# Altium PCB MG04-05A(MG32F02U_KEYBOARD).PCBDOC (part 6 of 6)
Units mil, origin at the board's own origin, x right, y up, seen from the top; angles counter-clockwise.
Board outline 17912.8 x 10422.68 mil, 2 copper layers (Top Layer, Bottom Layer); 623 components, 347 nets, 1816 pads, 821 vias.
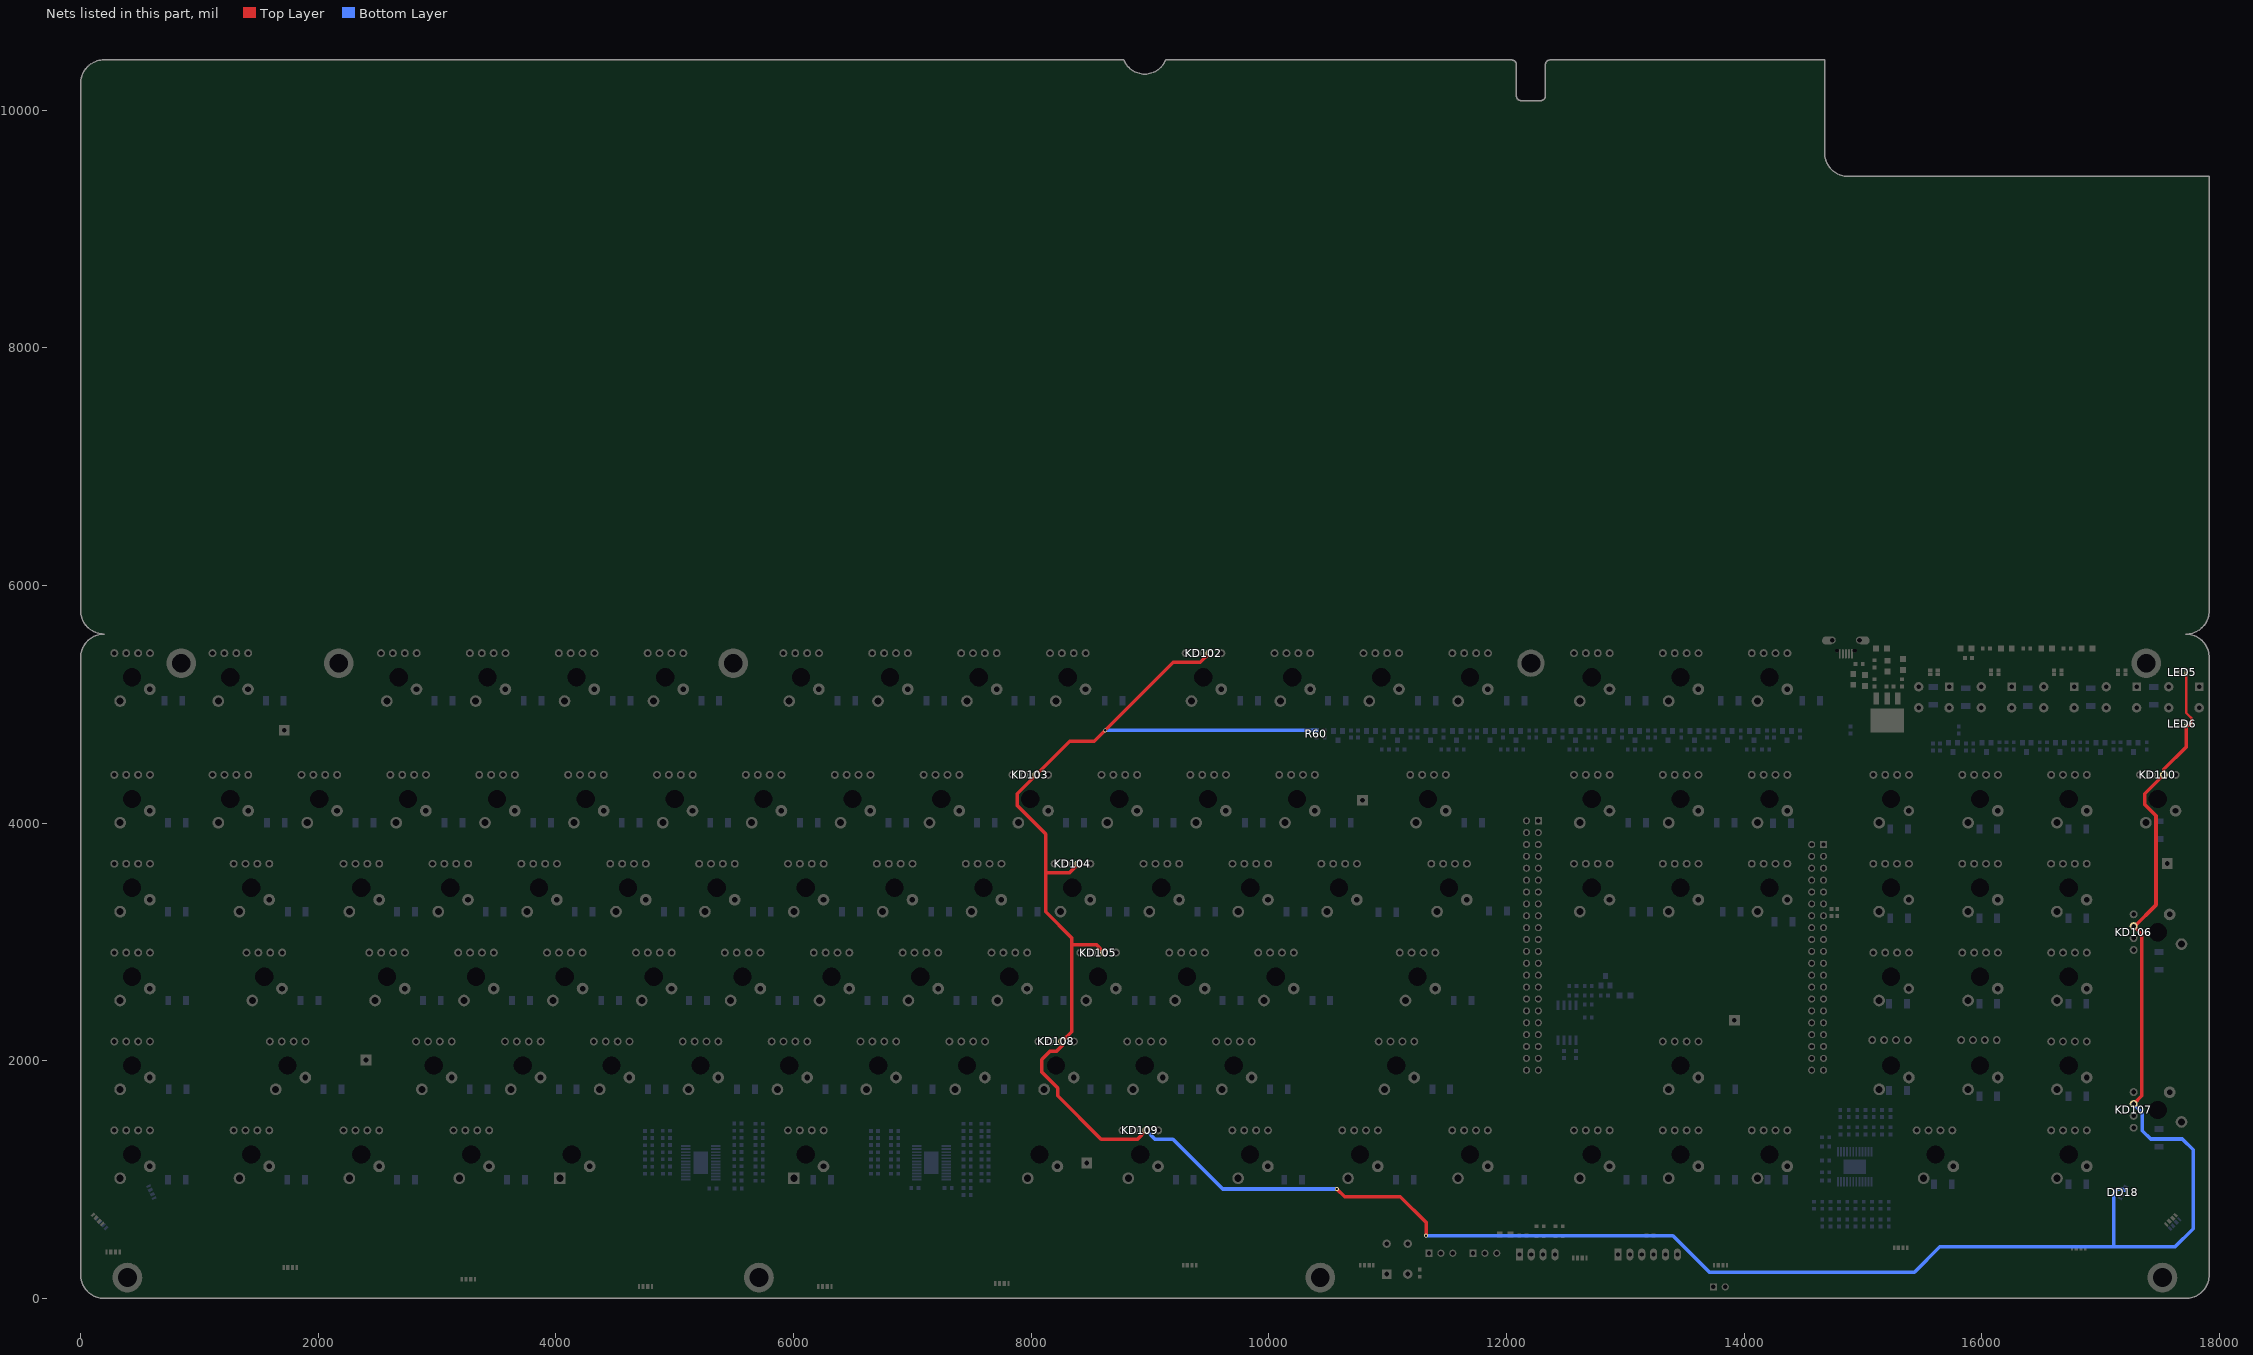
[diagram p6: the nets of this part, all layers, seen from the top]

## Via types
v1: diameter 30, hole 12, Top Layer to Bottom Layer, tented both sides, 273 vias
v2: diameter 26, hole 16, Top Layer to Bottom Layer, tented both sides, 181 vias
v3: diameter 26, hole 12, Top Layer to Bottom Layer, tented both sides, 165 vias
v4: diameter 33, hole 20, Top Layer to Bottom Layer, tented both sides, 61 vias
v5: diameter 25, hole 12, Top Layer to Bottom Layer, tented both sides, 47 vias
v6: diameter 20, hole 12, Top Layer to Bottom Layer, tented both sides, 40 vias
v7: diameter 30, hole 16, Top Layer to Bottom Layer, tented both sides, 30 vias
v8: diameter 28, hole 16, Top Layer to Bottom Layer, tented both sides, 12 vias
v9: diameter 35, hole 20, Top Layer to Bottom Layer, tented both sides, 5 vias
v10: diameter 25, hole 16, Top Layer to Bottom Layer, tented both sides, 3 vias
v11: diameter 40, hole 12, Top Layer to Bottom Layer, tented both sides, 3 vias
v12: diameter 40, hole 20, Top Layer to Bottom Layer, tented both sides, 1 vias

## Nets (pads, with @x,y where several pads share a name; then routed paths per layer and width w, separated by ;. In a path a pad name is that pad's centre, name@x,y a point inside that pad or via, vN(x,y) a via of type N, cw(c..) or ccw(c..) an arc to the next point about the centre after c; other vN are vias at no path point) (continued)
V_11: DD18.1 KD102.1 KD103.1 KD104.1 KD105.1 KD106.1 KD107.1 KD108.1 KD109.1 KD110.1 LED5.1 LED6.1 R60.2 | length 24323.9
  Top Layer w20: LED6.1@17718.5,4818.27 17747,4818.27 17762,4833.27 17762,4885.7 17718.5,4929.2 LED5.1@17718.5,5253.27
  Top Layer w30: KD103.1@8042.3,4390.85 KD103.1@8042.3,4406.2 ; 8341.77,2540.1 8341.77,2977.8 ; KD104.1@8396.72,3657.8 8321.72,3582.8 8121.77,3582.8 ; KD105.1@8613.21,2910.2 8545.61,2977.8 8341.77,2977.8 ; KD109.1@8967.56,1414.1 8893.45,1340 8587,1340 8222,1705 8222,1770 8087,1905 8087,2010 8157,2080 8212,2080 8258.9,2126.89 KD108.1@8258.9,2162.1 8341.77,2244.98 8341.77,2977.8 ; KD102.1@9499.16,5429.8 9422.16,5352.8 9193.92,5352.8 8528.92,4687.8 8323.9,4687.8 KD103.1@8042.3,4406.2 ; v4(10571.85,920.7) 10636.85,855.7 11105.97,855.7 11321.85,639.82 v4(11321.85,527.8) ; KD106.1@17274.6,3121.25 KD106.1@17281.23,3127.88 ; KD107.1@17276.48,1636.37 17344.6,1704.48 17344.6,3064.52 KD106.1@17281.23,3127.88 ; KD106.1@17276.68,3132.43 KD106.1@17281.23,3127.88 ; LED6.1@17718.5,4811.7 17718.5,4640.15 17530.07,4451.72 17530.07,4406.72 17369.6,4246.25 17369.6,4156.25 17464.6,4061.25 17464.6,3311.25 KD106.1@17281.23,3127.88 ; KD103.1@8042.3,4406.2 7881.77,4245.67 7881.77,4147.8 8121.77,3907.8 8121.77,3582.8 ; 8121.77,3582.8 8121.77,3252.8 8341.77,3032.8 8341.77,2977.8
  Bottom Layer w30: v4(8622,4780) R60.2@10400,4780 ; KD109.1@8960.22,1414.1 KD109.1@8967.56,1414.1 9040.96,1340.7 9191.85,1340.7 9611.85,920.7 v4(10571.85,920.7) ; v4(11321.85,527.8) 13399.74,527.8 13706.85,220.7 15431.81,220.7 15644.6,433.48 17109.6,433.48 ; DD18.1@17195.25,909.49 17186.26,918.48 17139.6,918.48 17109.6,888.48 17109.6,433.48 ; KD107.1@17276.48,1636.37 17349.6,1563.25 17349.6,1411.25 17419.6,1341.25 17687,1341.25 17777,1251.25 17777,1081.25 ; 17777,1116.08 17777,1081.25 ; 17109.6,433.48 17624.6,433.48 17777,585.88 17777,1081.25
pads on no net: CN1.3 CN1.4 CN1.5 CN1.6 CN1.7 CN1.8 CN1.16 CN1.21 CN1.22 CN1.23 CN1.24 CN1.26 CN2.3 CN2.19 CN2.20 CN2.33 CN2.34 CN2.35 CN2.36 CN2.41 CN2.42 CN2.43 CN2.44 CN3.6 SW1.0 SW2.0 SW3.0 SW4.0 SW5.0 SW6.0 SW7.0 SW8.0 SW9.0 SW10.0 SW11.0 SW12.0 SW13.0 SW14.0 SW15.0 SW16.0 SW17.0 SW18.0 SW19.0 SW20.0 SW21.0 SW22.0 SW23.0 SW24.0 SW25.0 SW26.0 SW27.0 SW28.0 SW29.0 SW30.0 SW31.0 SW32.0 SW33.0 SW34.0 SW35.0 SW36.0 SW37.0 SW38.0 SW39.0 SW40.0 SW41.0 SW42.0 SW43.0 SW44.0 SW45.0 SW46.0 SW47.0 SW48.0 SW49.0 SW50.0 SW51.0 SW52.0 SW53.0 SW54.0 SW55.0 SW56.0 SW57.0 SW58.0 SW59.0 SW60.0 SW61.0 SW62.0 SW63.0 SW64.0 SW65.0 SW66.0 SW67.0 SW68.0 SW69.0 SW70.0 SW71.0 SW72.0 SW73.0 SW74.0 SW75.0 SW76.0 SW77.0 SW78.0 SW79.0 SW80.0 SW81.0 SW82.0 SW83.0 SW84.0 SW85.0 SW86.0 SW87.0 SW88.0 SW89.0 SW90.0 SW91.0 SW92.0 SW93.0 SW94.0 SW95.0 SW96.0 SW97.0 SW98.0 SW99.0 SW100.0 SW101.0 SW102.0 SW103.0 SW104.0 SW105.0 SW106.0 SW107.0 SW108.0 SW109.0 SW110.0 SW111.4 SW112.0 SW113.0 U1.5 U1.25 U2.5 U2.25 U4.5 U4.25
copper on no net:
  other v2: 197.15,758.42 197,5590.55 196.85,10422.68
  other v7: 5178.21,1057.49 5263.21,1057.49 7118.21,1057.49 7203.21,1057.49 14846.85,1065.7 14936.85,1065.7 15011.85,1065.7 14767,1106.47 5178.21,1147.49 5263.21,1147.49 7118.21,1147.49 7203.21,1147.49 14846.85,1150.7 14936.85,1150.7 15011.85,1150.7 5178.21,1222.49 5263.21,1222.49 7118.21,1222.49 7203.21,1222.49

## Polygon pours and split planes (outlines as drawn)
GND on Top Layer "Top Layer-No Net" (hatched 90Degree grid 20 track 20, remove dead copper, pour order 1000): 0,345.06 0,0.94 802,0.94 17929.6,-0.52 17929.6,5584.23 52.43,5585 8,5465.54
+VDD_LED on Top Layer "Top Layer-No Net" (hatched 90Degree grid 10 track 10, remove dead copper, pour order 1000): 13147,4816.47 13182,4781.47 13192,4781.47 13207,4811.47 13207,4871.47 13147,4871.47
no net on Top Layer "Top Layer-No Net" (hatched 90Degree grid 50 track 50, remove dead copper, pour order 1000): -50,5598.48 -50,10248.48 200,10498.48 17050,10498.48 17950,9598.48 17950,5698.48 17850,5598.48
GND on Bottom Layer "Top Layer-No Net" (hatched 90Degree grid 20 track 20, remove dead copper, pour order 1000): 0,345.06 0,0.94 802,0.94 17929.6,-0.52 17929.6,5584.23 52.43,5585 8,5465.54
+VDD_LED on Bottom Layer "Top Layer-No Net" (hatched 90Degree grid 10 track 10, remove dead copper, pour order 1001): 13132,4806.47 13202,4806.47 13232,4836.47 13232,4861.47 13132,4861.47
no net on Bottom Layer "Top Layer-No Net" (hatched 90Degree grid 50 track 50, remove dead copper, pour order 1000): -50,5598.48 -50,10248.48 200,10498.48 17050,10498.48 17950,9598.48 17950,5698.48 17850,5598.48

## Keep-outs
Keep-Out Layer:
  lines w7: 197.15,5584.06 8778.93,5584.06 ; 4869.6,5590.95 8809.6,5590.95 ; 9137,5586.85 17735.61,5586.85 ; 10493.34,5766.52 11046.49,5766.52 ; 10493.34,5766.52 10493.34,6319.67 ; 10493.34,5766.52 10493.34,6319.67 ; 10493.34,5766.52 11046.49,5766.52 ; 10493.34,6319.67 11046.49,6319.67 ; 10493.34,6319.67 11046.49,6319.67 ; 11046.49,5766.52 11046.49,6319.67 ; 11046.49,5766.52 11046.49,6319.67 ; 11418.54,5766.52 11971.7,5766.52 ; 11418.54,5766.52 11418.54,6319.67 ; 11418.54,5766.52 11418.54,6319.67 ; 11418.54,5766.52 11971.7,5766.52 ; 11418.54,6319.67 11971.7,6319.67 ; 11418.54,6319.67 11971.7,6319.67 ; 11971.7,5766.52 11971.7,6319.67 ; 11971.7,5766.52 11971.7,6319.67
  lines w8.8: -2.7,5393.85 -2.7,198.37 ccw(c195.01,197.71) 194.34,0 17715.75,0 ccw(c17715.75,196.85) 17912.6,196.85 ; -2.4,5387.21 cw(c194.45,5387.21) 194.45,5584.06 ; 194.15,5590.95 8778.93,5590.95 ; 196.85,5590.95 17715.95,5590.95 ; 8778.93,5590.7 ccw(c8954.69,5660.13) 9130.28,5590.26 ; 9130.28,5590.8 17715.95,5590.8 ; 17715.95,5586.85 cw(c17715.95,5390) 17912.8,5390 ; 17912.8,196.85 17912.8,5410
  lines w22: 196.85,5590.7 549.78,5590.7 579.78,5617.55 609.78,5637.55 634.78,5647.55 669.78,5657.55 694.78,5657.55 719.78,5657.55 744.78,5652.55 769.78,5642.55 799.78,5627.55 824.78,5607.55 839.78,5590.7 ; 196.85,5590.95 cw(c196.85,5787.8) 0,5787.8 0,10225.83 cw(c196.85,10225.83) 196.85,10422.68 8776.85,10422.68 ; 839.78,5590.95 4679.6,5590.95 4709.6,5617.8 4739.6,5637.8 4764.6,5647.8 4799.6,5657.8 4824.6,5657.8 4849.6,5657.8 4874.6,5652.8 4899.6,5642.8 4929.6,5627.8 4954.6,5607.8 4969.6,5590.95 8809.6,5590.95 8839.6,5617.8 8869.6,5637.8 8894.6,5647.8 8929.6,5657.8 8954.6,5657.8 8979.6,5657.8 9004.6,5652.8 9029.6,5642.8 9059.6,5627.8 9084.6,5607.8 9099.6,5590.95 17042,5590.95 17076.87,5590.95 17098.47,5612.55 17128.47,5632.55 17153.47,5642.55 17188.47,5652.55 17213.47,5652.55 17238.47,5652.55 17263.47,5647.55 17288.47,5637.55 17318.47,5622.55 17343.47,5602.55 17353.7,5591.05 17715.95,5591.05 ; 1465,6983.32 1402,6983.32 1402,7015.32 1271,7015.32 1140,7015.32 1140,6881.32 1105,6881.32 1105,6771.32 1140,6771.32 1140,6531.32 1211,6531.32 1211,6485.32 1331,6485.32 1331,6531.32 1402,6531.32 1402,6562.32 1466,6562.32 1466,6516.32 2016,6516.32 2016,6562.32 2080,6562.32 2080,6531.32 2151,6531.32 2151,6485.32 2271,6485.32 2271,6531.32 2342,6531.32 2342,6771.32 2377,6771.32 2377,6881.32 2342,6881.32 2342,7015.32 2211,7015.32 2080,7015.32 2080,6983.32 2017,6983.32 ; 1466,6983.32 1466,7066.32 2016,7066.32 2016,6983.32 ; 8778.93,10422.68 ccw(c8954.69,10492.11) 9130.28,10422.25 12042.69,10422.25 cw(c12042.7,10382.9) 12082.06,10382.89 ; 10795.74,6983.32 10732.74,6983.32 10732.74,7015.32 10601.74,7015.32 10470.74,7015.32 10470.74,6881.32 10435.74,6881.32 10435.74,6771.32 10470.74,6771.32 10470.74,6531.32 10541.74,6531.32 10541.74,6485.32 10661.74,6485.32 10661.74,6531.32 10732.74,6531.32 10732.74,6562.32 10796.74,6562.32 10796.74,6516.32 11346.74,6516.32 11346.74,6562.32 11410.74,6562.32 11410.74,6531.32 11481.74,6531.32 11481.74,6485.32 11601.74,6485.32 11601.74,6531.32 11672.74,6531.32 11672.74,6771.32 11707.74,6771.32 11707.74,6881.32 11672.74,6881.32 11672.74,7015.32 11541.74,7015.32 11410.74,7015.32 11410.74,6983.32 11347.74,6983.32 ; 10796.74,6983.32 10796.74,7066.32 11346.74,7066.32 11346.74,6983.32 ; 10972.93,7731.42 10909.93,7731.42 10909.93,7763.42 10778.93,7763.42 10647.93,7763.42 10647.93,7629.42 10612.93,7629.42 10612.93,7519.42 10647.93,7519.42 10647.93,7279.42 10718.93,7279.42 10718.93,7233.42 10838.93,7233.42 10838.93,7279.42 10909.93,7279.42 10909.93,7310.42 10973.93,7310.42 10973.93,7264.42 11523.93,7264.42 11523.93,7310.42 11587.93,7310.42 11587.93,7279.42 11658.93,7279.42 11658.93,7233.42 11778.93,7233.42 11778.93,7279.42 11849.93,7279.42 11849.93,7519.42 11884.93,7519.42 11884.93,7629.42 11849.93,7629.42 11849.93,7763.42 11718.93,7763.42 11587.93,7763.42 11587.93,7731.42 11524.93,7731.42 ; 10973.93,7731.42 10973.93,7814.42 11523.93,7814.42 11523.93,7731.42 ; 11061.55,9227.42 10998.55,9227.42 10998.55,9259.42 10867.55,9259.42 10736.55,9259.42 10736.55,9125.42 10701.55,9125.42 10701.55,9015.42 10736.55,9015.42 10736.55,8775.42 10807.55,8775.42 10807.55,8729.42 10927.55,8729.42 10927.55,8775.42 10998.55,8775.42 10998.55,8806.42 11062.55,8806.42 11062.55,8760.42 11612.55,8760.42 11612.55,8806.42 11676.55,8806.42 11676.55,8775.42 11747.55,8775.42 11747.55,8729.42 11867.55,8729.42 11867.55,8775.42 11938.55,8775.42 11938.55,9015.42 11973.55,9015.42 11973.55,9125.42 11938.55,9125.42 11938.55,9259.42 11807.55,9259.42 11676.55,9259.42 11676.55,9227.42 11613.55,9227.42 ; 11062.55,9227.42 11062.55,9310.42 11612.55,9310.42 11612.55,9227.42 ; 12082.06,10383.86 12082.06,10119.37 ccw(c12121.43,10119.37) 12121.43,10080 12286.78,10080 ccw(c12286.78,10119.37) 12326.15,10119.37 12326.15,10383.86 ; 12326.15,10382.89 cw(c12365.52,10382.88) 12365.52,10422.25 14676.35,10422.25 14676.35,9639.56 ccw(c14873.2,9639.56) 14873.2,9442.71 17912.8,9442.71 17912.8,5787.19 cw(c17715.95,5787.19) 17715.95,5590.34 ; 15333.34,6235.32 15270.34,6235.32 15270.34,6267.32 15139.34,6267.32 15008.34,6267.32 15008.34,6133.32 14973.34,6133.32 14973.34,6023.32 15008.34,6023.32 15008.34,5783.32 15079.34,5783.32 15079.34,5737.32 15199.34,5737.32 15199.34,5783.32 15270.34,5783.32 15270.34,5814.32 15334.34,5814.32 15334.34,5768.32 15884.34,5768.32 15884.34,5814.32 15948.34,5814.32 15948.34,5783.32 16019.34,5783.32 16019.34,5737.32 16139.34,5737.32 16139.34,5783.32 16210.34,5783.32 16210.34,6023.32 16245.34,6023.32 16245.34,6133.32 16210.34,6133.32 16210.34,6267.32 16079.34,6267.32 15948.34,6267.32 15948.34,6235.32 15885.34,6235.32 ; 15334.34,6235.32 15334.34,6318.32 15884.34,6318.32 15884.34,6235.32 ; 16699.36,9442.71 17321.68,9442.71 ; 17287.25,6141.32 17287.25,6078.32 17255.25,6078.32 17255.25,5947.32 17255.25,5816.32 17389.25,5816.32 17389.25,5781.32 17499.25,5781.32 17499.25,5816.32 17739.25,5816.32 17739.25,5887.32 17785.25,5887.32 17785.25,6007.32 17739.25,6007.32 17739.25,6078.32 17708.25,6078.32 17708.25,6142.32 17754.25,6142.32 17754.25,6692.32 17708.25,6692.32 17708.25,6756.32 17739.25,6756.32 17739.25,6827.32 17785.25,6827.32 17785.25,6947.32 17739.25,6947.32 17739.25,7018.32 17499.25,7018.32 17499.25,7053.32 17389.25,7053.32 17389.25,7018.32 17255.25,7018.32 17255.25,6887.32 17255.25,6756.32 17287.25,6756.32 17287.25,6693.32 ; 17287.25,6142.32 17204.25,6142.32 17204.25,6692.32 17287.25,6692.32 ; 17287.45,7637.38 17287.45,7574.38 17255.45,7574.38 17255.45,7443.38 17255.45,7312.38 17389.45,7312.38 17389.45,7277.38 17499.45,7277.38 17499.45,7312.38 17739.45,7312.38 17739.45,7383.38 17785.45,7383.38 17785.45,7503.38 17739.45,7503.38 17739.45,7574.38 17708.45,7574.38 17708.45,7638.38 17754.45,7638.38 17754.45,8188.38 17708.45,8188.38 17708.45,8252.38 17739.45,8252.38 17739.45,8323.38 17785.45,8323.38 17785.45,8443.38 17739.45,8443.38 17739.45,8514.38 17499.45,8514.38 17499.45,8549.38 17389.45,8549.38 17389.45,8514.38 17255.45,8514.38 17255.45,8383.38 17255.45,8252.38 17287.45,8252.38 17287.45,8189.38 ; 17287.45,7638.38 17204.45,7638.38 17204.45,8188.38 17287.45,8188.38 ; 158.99,5766.52 712.14,5766.52 712.14,6319.67 158.99,6319.67 158.99,5766.52 ; 158.99,6514.55 712.14,6514.55 712.14,7067.7 158.99,7067.7 158.99,6514.55 ; 158.99,7262.58 712.14,7262.58 712.14,7815.73 158.99,7815.73 158.99,7262.58 ; 158.99,8010.62 712.14,8010.62 712.14,8563.77 158.99,8563.77 158.99,8010.62 ; 158.99,8758.65 712.14,8758.65 712.14,9311.81 158.99,9311.81 158.99,8758.65 ; 158.99,9782.28 712.14,9782.28 712.14,10335.43 158.99,10335.43 158.99,9782.28 ; 982.61,8758.65 1535.76,8758.65 1535.76,9311.81 982.61,9311.81 982.61,8758.65 ; 982.61,9782.28 1535.76,9782.28 1535.76,10335.43 982.61,10335.43 982.61,9782.28 ; 1159.78,5766.52 1712.93,5766.52 1712.93,6319.67 1159.78,6319.67 1159.78,5766.52 ; 1159.78,8010.62 1712.93,8010.62 1712.93,8563.77 1159.78,8563.77 1159.78,8010.62 ; 1268.04,7262.58 1268.04,7815.73 1821.19,7815.73 1821.19,7262.58 1268.04,7262.58 ; 1730.64,8758.65 2283.79,8758.65 2283.79,9311.81 1730.64,9311.81 1730.64,8758.65 ; 2084.98,5766.52 2638.13,5766.52 2638.13,6319.67 2084.98,6319.67 2084.98,5766.52 ; 2084.98,8010.62 2638.13,8010.62 2638.13,8563.77 2084.98,8563.77 2084.98,8010.62 ; 2301.51,7262.58 2854.66,7262.58 2854.66,7815.73 2301.51,7815.73 2301.51,7262.58 ; 2399.94,9782.28 2953.09,9782.28 2953.09,10335.43 2399.94,10335.43 2399.94,9782.28 ; 2478.68,8758.65 3031.83,8758.65 3031.83,9311.81 2478.68,9311.81 2478.68,8758.65 ; 2695.21,6514.55 3248.36,6514.55 3248.36,7067.7 2695.21,7067.7 2695.21,6514.55 ; 2833.01,8010.62 3386.16,8010.62 3386.16,8563.77 2833.01,8563.77 2833.01,8010.62 ; 3010.17,5766.52 3563.33,5766.52 3563.33,6319.67 3010.17,6319.67 3010.17,5766.52 ; 3049.54,7262.58 3602.7,7262.58 3602.7,7815.73 3049.54,7815.73 3049.54,7262.58 ; 3147.97,9782.28 3701.13,9782.28 3701.13,10335.43 3147.97,10335.43 3147.97,9782.28 ; 3226.71,8758.65 3779.87,8758.65 3779.87,9311.81 3226.71,9311.81 3226.71,8758.65 ; 3443.24,6514.55 3996.4,6514.55 3996.4,7067.7 3443.24,7067.7 3443.24,6514.55 ; 3581.05,8010.62 4134.2,8010.62 4134.2,8563.77 3581.05,8563.77 3581.05,8010.62 ; 3797.58,7262.58 4350.73,7262.58 4350.73,7815.73 3797.58,7815.73 3797.58,7262.58 ; 3896.01,9782.28 4449.16,9782.28 4449.16,10335.43 3896.01,10335.43 3896.01,9782.28 ; 3972.29,6023.48 3972.29,6133.48 4007.29,6133.48 4007.29,6267.48 4138.29,6267.48 4269.29,6267.48 4269.29,6133.48 5828.29,6133.48 5828.29,6318.48 6378.29,6318.48 6378.29,6133.48 7937.29,6133.48 7937.29,6267.48 8068.29,6267.48 8199.29,6267.48 8199.29,6133.48 8234.29,6133.48 8234.29,6023.48 8199.29,6023.48 8199.29,5783.48 8128.29,5783.48 8128.29,5737.48 8008.29,5737.48 8008.29,5783.48 7937.29,5783.48 7937.29,5953.48 6378.29,5953.48 6378.29,5768.48 5828.29,5768.48 5828.29,5953.48 4269.29,5953.48 4269.29,5783.48 4198.29,5783.48 4198.29,5737.48 4078.29,5737.48 4078.29,5783.48 4007.29,5783.48 4007.29,6023.48 3972.29,6023.48 ; 3974.75,8758.65 4527.9,8758.65 4527.9,9311.81 3974.75,9311.81 3974.75,8758.65 ; 4191.29,6514.55 4744.43,6514.55 4744.43,7067.7 4191.29,7067.7 4191.29,6514.55 ; 4329.08,8010.62 4882.23,8010.62 4882.23,8563.77 4329.08,8563.77 4329.08,8010.62 ; 4545.62,7262.58 5098.77,7262.58 5098.77,7815.73 4545.62,7815.73 4545.62,7262.58 ; 4644.04,9782.28 5197.19,9782.28 5197.19,10335.43 4644.04,10335.43 4644.04,9782.28 ; 4722.78,8758.65 5275.93,8758.65 5275.93,9311.81 4722.78,9311.81 4722.78,8758.65 ; 4939.32,6514.55 5492.47,6514.55 5492.47,7067.7 4939.32,7067.7 4939.32,6514.55 ; 5077.11,8010.62 5630.26,8010.62 5630.26,8563.77 5077.11,8563.77 5077.11,8010.62 ; 5293.65,7262.58 5846.8,7262.58 5846.8,7815.73 5293.65,7815.73 5293.65,7262.58 ; 5470.81,8758.65 6023.96,8758.65 6023.96,9311.81 5470.81,9311.81 5470.81,8758.65 ; 5687.35,6514.55 6240.5,6514.55 6240.5,7067.7 5687.35,7067.7 5687.35,6514.55 ; 5785.77,9782.28 6338.92,9782.28 6338.92,10335.43 5785.77,10335.43 5785.77,9782.28 ; 5825.14,8010.62 6378.29,8010.62 6378.29,8563.77 5825.14,8563.77 5825.14,8010.62 ; 6041.68,7262.58 6594.83,7262.58 6594.83,7815.73 6041.68,7815.73 6041.68,7262.58 ; 6218.84,8758.65 6771.99,8758.65 6771.99,9311.81 6218.84,9311.81 6218.84,8758.65 ; 6435.38,6514.55 6988.53,6514.55 6988.53,7067.7 6435.38,7067.7 6435.38,6514.55 ; 6533.8,9782.28 7086.95,9782.28 7086.95,10335.43 6533.8,10335.43 6533.8,9782.28 ; 6573.18,8010.62 7126.33,8010.62 7126.33,8563.77 6573.18,8563.77 6573.18,8010.62 ; 6789.71,7262.58 7342.86,7262.58 7342.86,7815.73 6789.71,7815.73 6789.71,7262.58 ; 6966.88,8758.65 7520.04,8758.65 7520.04,9311.81 6966.88,9311.81 6966.88,8758.65 ; 7183.41,6514.55 7736.57,6514.55 7736.57,7067.7 7183.41,7067.7 7183.41,6514.55 ; 7281.84,9782.28 7835,9782.28 7835,10335.43 7281.84,10335.43 7281.84,9782.28 ; 7321.21,8010.62 7874.37,8010.62 7874.37,8563.77 7321.21,8563.77 7321.21,8010.62 ; 7537.76,7262.58 8090.9,7262.58 8090.9,7815.73 7537.76,7815.73 7537.76,7262.58 ; 7714.92,8758.65 8268.07,8758.65 8268.07,9311.81 7714.92,9311.81 7714.92,8758.65 ; 7931.45,6514.55 7931.45,7067.7 8484.61,7067.7 8484.61,6514.55 7931.45,6514.55 ; 8029.88,9782.28 8583.03,9782.28 8583.03,10335.43 8029.88,10335.43 8029.88,9782.28 ; 8069.25,8010.62 8622.4,8010.62 8622.4,8563.77 8069.25,8563.77 8069.25,8010.62 ; 8285.79,7262.58 8838.93,7262.58 8838.93,7815.73 8285.79,7815.73 8285.79,7262.58 ; 8462.95,8758.65 9016.1,8758.65 9016.1,9311.81 8462.95,9311.81 8462.95,8758.65 ; 8640.12,5766.52 8640.12,6319.67 9193.27,6319.67 9193.27,5766.52 8640.12,5766.52 ; 8679.49,6514.55 8679.49,7067.7 9232.64,7067.7 9232.64,6514.55 8679.49,6514.55 ; 8817.28,8010.62 9370.43,8010.62 9370.43,8563.77 8817.28,8563.77 8817.28,8010.62 ; 9033.82,7262.58 9033.82,7815.73 9586.97,7815.73 9586.97,7262.58 9033.82,7262.58 ; 9171.61,9782.28 9724.76,9782.28 9724.76,10335.43 9171.61,10335.43 9171.61,9782.28 ; 9210.98,8758.65 9764.13,8758.65 9764.13,9311.81 9210.98,9311.81 9210.98,8758.65 ; 9427.52,6514.55 9427.52,7067.7 9980.67,7067.7 9980.67,6514.55 9427.52,6514.55 ; 9565.31,5766.52 9565.31,6319.67 10118.46,6319.67 10118.46,5766.52 9565.31,5766.52 ; 9565.31,8010.62 9565.31,8563.77 10118.46,8563.77 10118.46,8010.62 9565.31,8010.62 ; 9781.85,7262.58 9781.85,7815.73 10335,7815.73 10335,7262.58 9781.85,7262.58 ; 9919.64,9782.28 10472.79,9782.28 10472.79,10335.43 9919.64,10335.43 9919.64,9782.28 ; 9959.02,8758.65 9959.02,9311.81 10512.17,9311.81 10512.17,8758.65 9959.02,8758.65 ; 10313.34,8010.62 10313.34,8563.77 10866.49,8563.77 10866.49,8010.62 10313.34,8010.62 ; 10493.34,5766.52 10493.34,6319.67 11046.49,6319.67 11046.49,5766.52 10493.34,5766.52 ; 10667.68,9782.28 11220.83,9782.28 11220.83,10335.43 10667.68,10335.43 10667.68,9782.28 ; 11238.54,8010.62 11238.54,8563.77 11791.7,8563.77 11791.7,8010.62 11238.54,8010.62 ; 11415.72,9782.28 11415.72,10335.43 11968.87,10335.43 11968.87,9782.28 11415.72,9782.28 ; 11418.54,5766.52 11418.54,6319.67 11971.7,6319.67 11971.7,5766.52 11418.54,5766.52 ; 12439.34,5766.52 12439.34,6319.67 12992.49,6319.67 12992.49,5766.52 12439.34,5766.52 ; 12439.34,8010.62 12439.34,8563.77 12992.49,8563.77 12992.49,8010.62 12439.34,8010.62 ; 12439.34,8758.65 12439.34,9311.81 12992.49,9311.81 12992.49,8758.65 12439.34,8758.65 ; 12439.34,9782.28 12439.34,10335.43 12992.49,10335.43 12992.49,9782.28 12439.34,9782.28 ; 13187.37,5766.52 13187.37,6319.67 13740.52,6319.67 13740.52,5766.52 13187.37,5766.52 ; 13187.37,6514.55 13187.37,7067.7 13740.52,7067.7 13740.52,6514.55 13187.37,6514.55 ; 13187.37,8010.62 13187.37,8563.77 13740.52,8563.77 13740.52,8010.62 13187.37,8010.62 ; 13187.37,8758.65 13187.37,9311.81 13740.52,9311.81 13740.52,8758.65 13187.37,8758.65 ; 13187.37,9782.28 13187.37,10335.43 13740.52,10335.43 13740.52,9782.28 13187.37,9782.28 ; 13935.41,5766.52 13935.41,6319.67 14488.56,6319.67 14488.56,5766.52 13935.41,5766.52 ; 13935.41,8010.62 13935.41,8563.77 14488.56,8563.77 14488.56,8010.62 13935.41,8010.62 ; 13935.41,8758.65 13935.41,9311.81 14488.56,9311.81 14488.56,8758.65 13935.41,8758.65 ; 13935.41,9782.28 13935.41,10335.43 14488.56,10335.43 14488.56,9782.28 13935.41,9782.28 ; 14959.03,6514.55 14959.03,7067.7 15512.19,7067.7 15512.19,6514.55 14959.03,6514.55 ; 14959.03,7262.58 14959.03,7815.73 15512.19,7815.73 15512.19,7262.58 14959.03,7262.58 ; 14959.03,8010.62 14959.03,8563.77 15512.19,8563.77 15512.19,8010.62 14959.03,8010.62 ; 14959.03,8758.65 14959.03,9311.81 15512.19,9311.81 15512.19,8758.65 14959.03,8758.65 ; 15707.07,6514.55 15707.07,7067.7 16260.22,7067.7 16260.22,6514.55 15707.07,6514.55 ; 15707.07,7262.58 15707.07,7815.73 16260.22,7815.73 16260.22,7262.58 15707.07,7262.58 ; 15707.07,8010.62 15707.07,8563.77 16260.22,8563.77 16260.22,8010.62 15707.07,8010.62 ; 15707.07,8758.65 15707.07,9311.81 16260.22,9311.81 16260.22,8758.65 15707.07,8758.65 ; 16455.1,5766.52 16455.1,6319.67 17008.25,6319.67 17008.25,5766.52 16455.1,5766.52 ; 16455.1,6514.55 16455.1,7067.7 17008.25,7067.7 17008.25,6514.55 16455.1,6514.55 ; 16455.1,7262.58 16455.1,7815.73 17008.25,7815.73 17008.25,7262.58 16455.1,7262.58 ; 16455.1,8010.62 16455.1,8563.77 17008.25,8563.77 17008.25,8010.62 16455.1,8010.62 ; 16455.1,8758.65 16455.1,9311.81 17008.25,9311.81 17008.25,8758.65 16455.1,8758.65 ; 17203.13,8758.65 17203.13,9311.81 17756.28,9311.81 17756.28,8758.65 17203.13,8758.65

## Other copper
Top Layer:
  region: 5286.85,1240.7 5156.85,1240.7 5156.85,1040.7 5286.85,1040.7
  region: 7226.85,1240.7 7096.85,1240.7 7096.85,1040.7 7226.85,1040.7
  region: 15030.06,1042.05 15030.06,1172.05 14830.06,1172.05 14830.06,1042.05
Bottom Layer:
  rectangle net +3V3_LDO: 15059.85,4761.7 15341.85,4970.7

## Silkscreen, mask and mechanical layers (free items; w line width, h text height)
Top Overlay:
  lines w4: 1105,6791.32 1271,6791.32 ; 1121,6791.32 1271,6791.32 ; 1251,6791.32 1271,6791.32 ; 1271,6811.32 1271,6791.32 ; 1271,7015.32 1271,6791.32 ; 2211,6811.32 2211,6791.32 ; 2211,7015.32 2211,6791.32 ; 2351,6791.32 2211,6791.32 ; 2377,6791.32 2211,6791.32 ; 10435.74,6791.32 10601.74,6791.32 ; 10451.74,6791.32 10601.74,6791.32 ; 10581.74,6791.32 10601.74,6791.32 ; 10601.74,6811.32 10601.74,6791.32 ; 10601.74,7015.32 10601.74,6791.32 ; 10612.93,7539.42 10778.93,7539.42 ; 10628.93,7539.42 10778.93,7539.42 ; 10701.55,9035.42 10867.55,9035.42 ; 10717.55,9035.42 10867.55,9035.42 ; 10758.93,7539.42 10778.93,7539.42 ; 10778.93,7559.42 10778.93,7539.42 ; 10778.93,7763.42 10778.93,7539.42 ; 10847.55,9035.42 10867.55,9035.42 ; 10867.55,9055.42 10867.55,9035.42 ; 10867.55,9259.42 10867.55,9035.42 ; 11541.74,6811.32 11541.74,6791.32 ; 11541.74,7015.32 11541.74,6791.32 ; 11681.74,6791.32 11541.74,6791.32 ; 11707.74,6791.32 11541.74,6791.32 ; 11718.93,7559.42 11718.93,7539.42 ; 11718.93,7763.42 11718.93,7539.42 ; 11807.55,9055.42 11807.55,9035.42 ; 11807.55,9259.42 11807.55,9035.42 ; 11858.93,7539.42 11718.93,7539.42 ; 11884.93,7539.42 11718.93,7539.42 ; 11947.55,9035.42 11807.55,9035.42 ; 11973.55,9035.42 11807.55,9035.42 ; 12366.25,5643.6 14677.09,5643.6 14677.09,4809.94 ccw(c14873.94,4809.94) 14873.94,4613.09 17933.2,4613.09 ; 14973.34,6043.32 15139.34,6043.32 ; 14989.34,6043.32 15139.34,6043.32 ; 15119.34,6043.32 15139.34,6043.32 ; 15139.34,6063.32 15139.34,6043.32 ; 15139.34,6267.32 15139.34,6043.32 ; 16079.34,6063.32 16079.34,6043.32 ; 16079.34,6267.32 16079.34,6043.32 ; 16219.34,6043.32 16079.34,6043.32 ; 16245.34,6043.32 16079.34,6043.32 ; 17255.25,5947.32 17479.25,5947.32 ; 17255.25,6887.32 17479.25,6887.32 ; 17255.45,7443.38 17479.45,7443.38 17479.45,7277.38 ; 17255.45,8383.38 17479.45,8383.38 17479.45,8549.38 ; 17459.25,5947.32 17479.25,5947.32 ; 17459.25,6887.32 17479.25,6887.32 ; 17479.25,5781.32 17479.25,5947.32 ; 17479.25,5797.32 17479.25,5947.32 ; 17479.25,5927.32 17479.25,5947.32 ; 17479.25,7027.32 17479.25,6887.32 ; 17479.25,7053.32 17479.25,6887.32 ; 4138.29,6043.48 4138.29,6267.48 4138.29,6043.48 ; 4138.29,6043.48 3972.29,6043.48 4138.29,6043.48 ; 8068.29,6043.48 8068.29,6267.48 8068.29,6043.48 ; 8068.29,6043.48 8234.29,6043.48 8068.29,6043.48 ; 12048.89,1579.06 14804.8,1579.06 14804.8,4334.96 12048.89,4334.96 12048.89,1579.06
  lines w5: 17427.12,7913.38 17479.45,7913.38 17479.45,7862.2 ; 1741,6791.32 1689.82,6791.32 1741,6791.32 ; 1741,6791.32 1741,6843.64 1741,6791.32 ; 6103.29,6043.48 6052.11,6043.48 6103.29,6043.48 ; 6103.29,6043.48 6103.29,6095.81 6103.29,6043.48 ; 11071.74,6791.32 11020.56,6791.32 11071.74,6791.32 ; 11071.74,6791.32 11071.74,6843.64 11071.74,6791.32 ; 11248.93,7539.42 11197.75,7539.42 11248.93,7539.42 ; 11248.93,7539.42 11248.93,7591.74 11248.93,7539.42 ; 11337.55,9035.42 11286.37,9035.42 11337.55,9035.42 ; 11337.55,9035.42 11337.55,9087.74 11337.55,9035.42 ; 15609.34,6043.32 15558.16,6043.32 15609.34,6043.32 ; 15609.34,6043.32 15609.34,6095.64 15609.34,6043.32 ; 17479.25,6417.32 17479.25,6366.14 17479.25,6417.32 ; 17479.25,6417.32 17426.93,6417.32 17479.25,6417.32
  lines w7: 788.78,5345.98 846.53,5345.98 846.53,5405.08 ; 5492.2,5394.49 5492.2,5345.98 5540.7,5345.98 ; 12204.8,5394.49 12204.8,5345.98 12253.3,5345.98 ; 17381.96,5405.08 17381.96,5345.98 17439.7,5345.98
  lines w10: 12759.25,2502.48 13237,2502.48 13237,2642 12759.25,2642 12759.25,2502.48 ; 12783,2522 13217,2522 13217,2622 12783,2622 12783,2522 ; 13134.25,7355.88 13134.25,7495.4 13654.6,7495.4 13654.6,7355.88 13134.25,7355.88 ; 13158,7375.4 13158,7475.4 13634.6,7475.4 13634.6,7375.4 13158,7375.4
  lines w11.81: 393.3,267.65 393.3,175.65 484.22,175.65 ; 5708.26,267.65 5708.26,175.65 5799.18,175.65 ; 10432.67,267.65 10432.67,175.65 10523.59,175.65 ; 17519.28,267.65 17519.28,175.65 17610.21,175.65
  text "G32F02U_KEYBOARD" at 13683,7445.4 h45
  text "MG04-05UA" at 13188,7401.92 h50
  text "2021.06" at 13683,7375.4 h30
  text "center-center" at 5913.29,6383.48 h30
  text "SW2_KS4Bx6 dummy" at 5863.29,6343.48 h30
  text "F1" at 2369.3,5174.31 h78.74 r90
  text "F2" at 3117.3,5161.31 h78.74 r90
  text "F3" at 3865.3,5161.31 h78.74 r90
  text "F4" at 4613.3,5161.31 h78.74 r90
  text "F5" at 5755.3,5161.31 h78.74 r90
  text "F6" at 6502.3,5161.31 h78.74 r90
  text "F7" at 7250.3,5161.31 h78.74 r90
  text "F8" at 7998.3,5161.31 h78.74 r90
  text "F9" at 9140.3,5161.31 h78.74 r90
  text "F11" at 10636.3,5141.31 h78.74 r90
  text "F10" at 9888.3,5128.31 h78.74 r90
  text "F12" at 11384.3,5128.31 h78.74 r90
  text "Prof" at 124.3,5095.31 h78.74 r90
  text "ESC" at 947,4940 h78.74 r90
  text "Print Scrn" at 12408.3,4859.31 h70 r90
  text "Scroll Lock" at 13156.3,4826.31 h70 r90
  text "Pause Break" at 13904.3,4813.31 h70 r90
  text "GND" at 1646.85,4655.7 h50
  text "1" at 1699.3,4190.31 h78.74 r90
  text "2" at 2447.3,4177.31 h78.74 r90
  text "3" at 3195.3,4177.31 h78.74 r90
  text "4" at 3943.3,4177.31 h78.74 r90
  text "5" at 4691.3,4177.31 h78.74 r90
  text "6" at 5439.3,4177.31 h78.74 r90
  text "7" at 6187.3,4177.31 h78.74 r90
  text "8" at 6935.3,4177.31 h78.74 r90
  text "9" at 7683.3,4177.31 h78.74 r90
  text "M1" at 124.3,4151.31 h78.74 r90
  text "10" at 8431.3,4144.31 h78.74 r90
  text "`~" at 991.3,4137.31 h78.74 r90
  text "-_" at 9166.3,4137.31 h78.74 r90
  text "+=" at 9941.3,4137.31 h78.74 r90
  text "N/" at 15676.3,4137.31 h78.74 r90
  text "N*" at 16424.3,4137.31 h78.74 r90
  text "N-" at 17172.31,4137.31 h78.74 r90
  text "INS" at 12408.3,4105.31 h78.74 r90
  text "GND" at 10736.85,4070.7 h50
  text "Home" at 13156.3,4059.31 h78.74 r90
  text "Page Up" at 13878.3,3941.31 h70 r90
  text "Num Lock" at 14928.3,3908.31 h78.74 r90
  text "BackSpace" at 11004.3,3862.31 h78.74 r90
  text "GND" at 17501.85,3520.7 h50
  text "I" at 7290.3,3441.31 h78.74 r90
  text "W" at 2802.3,3428.31 h78.74 r90
  text "E" at 3550.3,3428.31 h78.74 r90
  text "R" at 4298.3,3428.31 h78.74 r90
  text "T" at 5046.3,3428.31 h78.74 r90
  text "Y" at 5794.3,3428.31 h78.74 r90
  text "U" at 6542.3,3428.31 h78.74 r90
  text "O" at 8038.3,3428.31 h78.74 r90
  text "P" at 8786.3,3428.31 h78.74 r90
  text "Q" at 2001.3,3415.31 h78.74
  text "\|" at 11207.3,3415.31 h78.74 r90
  text "[{" at 9534.3,3402.31 h78.74 r90
  text "]}" at 10282.3,3402.31 h78.74 r90
  text "M2" at 124.3,3389.31 h78.74 r90
  text "N7" at 14927.3,3389.31 h78.74 r90
  text "N8" at 15676.3,3389.31 h78.74 r90
  text "N9" at 16423.3,3389.31 h78.74 r90
  text "N+" at 17409.6,3386.25 h78.74
  text "TAB" at 1128.3,3350.31 h78.74 r90
  text "END" at 13156.3,3350.31 h78.74 r90
  text "Delete" at 12408.3,3245.31 h78.74 r90
  text "Page Down" at 13878.3,3113.31 h70 r90
  text "'\"" at 9803.3,2700.31 h78.74 r90
  text "A" at 2270.3,2681.31 h78.74 r90
  text "S" at 3018.3,2681.31 h78.74 r90
  text "D" at 3766.3,2681.31 h78.74 r90
  text "F" at 4514.3,2681.31 h78.74 r90
  text "G" at 5262.3,2681.31 h78.74 r90
  text "H" at 6010.3,2681.31 h78.74 r90
  text "J" at 6758.3,2681.31 h78.74 r90
  text "K" at 7506.3,2681.31 h78.74 r90
  text "L" at 8254.3,2681.31 h78.74 r90
  text ";:" at 8989.3,2668.31 h78.74 r90
  text "M3" at 124.3,2641.31 h78.74 r90
  text "N4" at 14927.3,2641.31 h78.74 r90
  text "N5" at 15676.3,2641.31 h78.74 r90
  text "N6" at 16424.3,2641.31 h78.74 r90
  text "G32F02U_KEYBOARD" at 13343,2592 h45
  text "MG04-05A" at 12813,2548.52 h50
  text "Enter" at 10941.3,2536.31 h78.74 r90
  text "2021.06" at 13343,2522 h30
  text "Caps Lock" at 1210.3,2372.31 h78.74 r90
  text "GND" at 13851.85,2205.7 h50
  text "Z" at 2664.3,1933.31 h78.74 r90
  text "X" at 3412.3,1933.31 h78.74 r90
  text "C" at 4160.3,1933.31 h78.74 r90
  text "V" at 4908.3,1933.31 h78.74 r90
  text "B" at 5656.3,1933.31 h78.74 r90
  text "N" at 6404.3,1933.31 h78.74 r90
  text "M" at 7152.3,1933.31 h78.74 r90
  text ".>" at 8648.3,1906.31 h78.74 r90
  text "/1" at 9396.3,1906.31 h78.74 r90
  text "N1" at 14928.3,1906.31 h78.74 r90
  text ",<" at 7874.3,1900.31 h78.74 r90
  text "N-Enter" at 17223.72,1894.97 h78.74
  text "M4" at 124.3,1893.31 h78.74 r90
  text "N2" at 15676.3,1893.31 h78.74 r90
  text "N3" at 16424.3,1893.31 h78.74 r90
  text "GND" at 2326.85,1870.7 h50
  text "UP-L" at 13156.3,1815.31 h78.74 r90
  text "L-SHIFT" at 1433.3,1703.31 h78.74 r90
  text "R-SHIFT" at 10764.3,1703.31 h78.74 r90
  text "M6" at 124.3,1145.31 h78.74 r90
  text "FN" at 9533.3,1145.31 h78.74 r90
  text "N0" at 15302.3,1145.31 h78.74 r90
  text "APP" at 10458.3,1106.31 h78.74 r90
  text "DEL" at 16424.3,1073.31 h78.74 r90
  text "L-WIN" at 2053.3,1034.31 h78.74 r90
  text "L-ALT" at 2979.3,1027.31 h78.74 r90
  text "R-ALT" at 8609.3,1027.31 h78.74 r90
  text "GND" at 8386.85,1010.7 h50
  text "L-Ctrl" at 1128.3,1008.31 h78.74 r90
  text "R-Ctrl" at 11383.3,1008.31 h78.74 r90
  text "Space1" at 5767.3,1001.31 h78.74 r90
  text "Left-L" at 12408.3,1001.31 h78.74 r90
  text "Space2" at 7737,990 h78.74 r90
  text "Down-L" at 13156.3,988.31 h78.74 r90
  text "Space3" at 4517,975 h78.74 r90
  text "Right-L" at 13878.3,962.31 h78.74 r90
  text "SWSRST" at 12947,570 h40 r90
  text "GND" at 13037,570 h40 r90
  text "SWDIO" at 13147,570 h40 r90
  text "VDD" at 13257,570 h40 r90
  text "SWCLK" at 13347,570 h40 r90
  text "PW" at 12129.6,113.48 h40 r90
  text "GND" at 12227,110 h40 r90
  text "RXD" at 12327,110 h40 r90
  text "TXD" at 12427,110 h40 r90
  text "SWD" at 13137,30 h40
  text "UART" at 12202,26.47 h40
Bottom Overlay:
  text "Chip Reset" at 11207,90 h40
Bottom Solder:
  region: 15341.85,4970.7 15059.85,4970.7 15059.85,4761.7 15341.85,4761.7
Mechanical 1:
  drawing of 815 lines, arcs and shapes, not listed
  text "V-CUT  殘厚小於 0.5mm" at -70.38,5611.59 h118.11 r90
Mechanical 3:
  drawing of 6290 lines, arcs and shapes, not listed
Mechanical 4:
  drawing of 983 lines, arcs and shapes, not listed
Mechanical 5:
  circle w11.11: c1764.98,3838.29 r110.24
  circle w11.11: c15777.5,3838.29 r110.24
  circle w11.11: c16624.61,3169.29 r157.48
  circle w11.11: c13379.61,3169.29 r157.48
  circle w11.11: c10537.61,3169.29 r157.48
  circle w11.11: c7501.61,3169.29 r157.48
  circle w11.11: c4505.61,3169.29 r157.48
  circle w11.11: c1406.61,3169.29 r157.48
  lines w11.11: 332.52,4076.93 481.49,3927.97 cw(c438.64,3897.36) 481.49,3866.76 333.34,3718.31 333.34,2545.8 481.01,2398.14 cw(c438.16,2367.54) 481.01,2336.93 332.86,2188.48 ; 332.61,2188.48 332.61,1064.87 774.98,748.03 2197.35,748.03 2388.9,939.58 cw(c2419.5,896.74) 2450.1,939.58 2641.65,748.03 4671.06,748.03 ; 332.61,4076.93 332.61,4721.98 726.31,4721.98 726.31,5401.12 977.61,5590.7 4236.62,5590.7 ccw(c4412.27,5660.41) 4587.86,5590.55 5106.09,5590.55 5223.74,5473.16 ccw(c5254.34,5516) 5284.94,5473.16 5402.33,5590.55 8385.69,5590.55 8494.38,5481.86 ccw(c8524.13,5523.5) 8553.88,5481.86 8662.8,5590.55 8680.51,5590.55 ; 8680.51,5590.7 ccw(c8856.27,5660.13) 9031.86,5590.26 ; 8801.3,747.25 8232.38,747.25 8040.66,938.58 ccw(c8010.05,895.74) 7979.45,938.58 7788.9,748.03 7775.61,748.03 4978.34,748.03 ; 8801.3,747.76 cw(c8954.63,637.3) 9107.43,748.48 ; 9031.86,5590.55 11647.27,5590.55 ; 9107.43,748.03 11489.69,748.03 11680.24,938.58 cw(c11710.84,895.74) 11741.44,938.58 11931.99,748.03 12833.26,748.03 ; 11647.27,5590.38 11755.1,5482.77 ccw(c11784.85,5524.42) 11814.6,5482.77 11922.67,5590.62 13125.23,5590.62 ; 12833.13,748.12 cw(c12986.2,637.3) 13139.77,747.43 13180.76,747.43 ; 13125.23,5590.7 ccw(c13300.99,5660.13) 13476.67,5590.51 ; 13181.6,748.03 13184.6,748.03 13373.15,936.58 cw(c13403.75,893.74) 13434.36,936.58 13622.91,748.03 13864.58,748.03 13864.58,944.88 14596.47,944.88 14596.47,748.03 16937.46,748.03 17379.86,1064.89 17379.86,2218.49 17305.26,2293.09 cw(c17346.91,2322.83) 17305.26,2352.58 17380.21,2427.68 17380.21,3715.49 ; 13476.67,5590.55 14222.86,5590.55 14222.86,4850.4 14524.13,4850.4 ccw(c14525.54,4948.82) 14623.95,4947.44 14623.95,5199.03 15710.49,5199.03 15710.49,4949.14 ; 15710.5,4948.82 ccw(c15808.92,4948.82) 15907.34,4947.44 ; 15907.34,4947.76 15907.34,5199.03 17096.46,5199.03 17096.46,4665.35 17379.86,4665.35 17379.86,3925.49 17304.92,3850.39 ccw(c17346.57,3820.64) 17304.92,3790.89 17380.17,3715.49 ; 4671.06,748.03 cw(c4824.71,638.02) 4978.34,748.06 ; 4671.06,748.03 cw(c4824.71,638.02) 4978.34,748.06 ; 8732.22,4629.92 8980.25,4629.92 8980.25,4937.01 8732.22,4937.01 ; 8732.22,4629.92 8732.22,4937.01 ; 8732.22,4629.92 8732.22,4937.01 ; 2064.9,3059.06 2427.1,3059.06 2427.1,3279.53 2064.9,3279.53 2064.9,3059.06 ; 15686.9,3055.12 15686.9,3283.46 16056.98,3283.46 16056.98,3055.12 15686.9,3055.12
